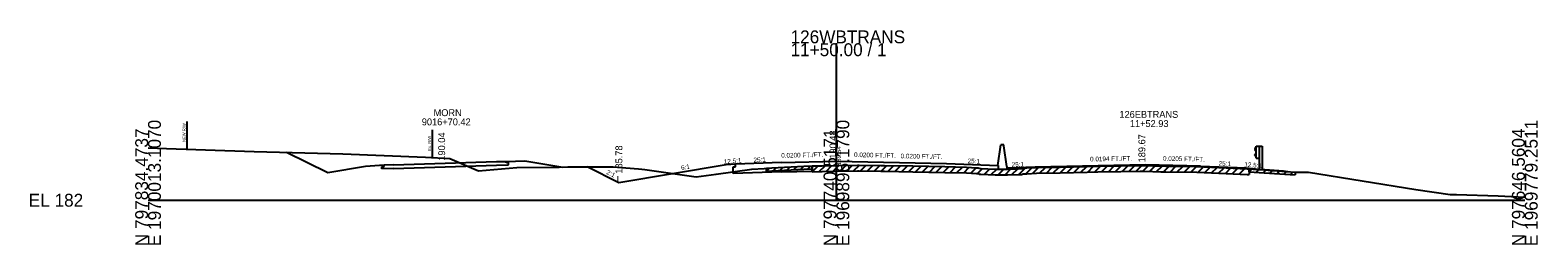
# Model space of a CAD drawing. Extents: x -6494 to 1970605, y -10 to 798140.
# Drawn here: x -25.7 to 302.8, y 3990.3 to 4037 of the extents above; entities that cross this region are included whole.
import ezdxf

# ---------------------------------------------------------------- set-up
doc = ezdxf.new("R2010")
doc.units = 0
for name, color, linetype in [('RD_GPK_XS_Cell', 7, 'Continuous'), ('RD_XS_Base', 7, 'Continuous'), ('RD_XS_EarthShd', 7, 'Continuous'), ('RD_XS_ExGround', 7, 'Continuous'), ('RD_XS_ExPaveRet', 7, 'Continuous'), ('RD_XS_ExRW', 7, 'Continuous'), ('RD_XS_GR', 7, 'Continuous'), ('RD_XS_MedBWall', 7, 'Continuous'), ('RD_XS_Misc_Line', 7, 'Continuous'), ('RD_XS_NewRW', 7, 'Continuous'), ('RD_XS_Pave', 7, 'Continuous'), ('RD_XS_PaveOvlay', 7, 'Continuous'), ('RD_XS_PaveShd', 7, 'Continuous'), ('RD_XS_TieSlope', 7, 'Continuous'), ('RD_XS_TX_Elev_EX', 7, 'Continuous'), ('RD_XS_TX_Elev_PR', 7, 'Continuous'), ('RD_XS_TX_Misc', 7, 'Continuous'), ('RD_XS_TX_MkPT', 7, 'Continuous'), ('RD_XS_TX_Profile', 7, 'Continuous'), ('RD_XS_TX_ShdSlope', 7, 'Continuous'), ('RD_XS_TX_Slope', 7, 'Continuous'), ('RD_XS_TX_Station', 7, 'Continuous')]:
    doc.layers.add(name, color=color, linetype=linetype)

msp = doc.modelspace()

# ---------------------------------------------------------------- linework, layer by layer
at = {"layer": 'RD_GPK_XS_Cell'}
for p, q in [((150, 4000), (150, 4034.13)), ((0, 4000), (150, 4000)), ((150, 4000), (300, 4000))]:
    msp.add_line(p, q, dxfattribs=at)
at = {"layer": 'RD_XS_Base'}
for p, q in [((78, 4008.15), (78, 4008.45)), ((78.51, 4008.17), (78, 4008.15)), ((78.51, 4007.69), (78.51, 4008.17)), ((50.93, 4007.31), (51.44, 4007.32)), ((50.93, 4006.83), (50.93, 4007.31)), ((53.48, 4006.91), (50.93, 4006.83)), ((51.44, 4007.32), (51.44, 4007.62)), ((75.96, 4007.61), (78.51, 4007.69)), ((127.5, 4007.26), (128, 4007.28)), ((127.5, 4005.78), (127.5, 4007.26)), ((138, 4006.2), (127.5, 4005.78)), ((128, 4007.28), (128, 4007.84)), ((138, 4006.2), (144.74, 4006.33)), ((239.31, 4006.86), (239.31, 4007.02))]:
    msp.add_line(p, q, dxfattribs=at)
at = {"layer": 'RD_XS_EarthShd'}
for p, q in [((78, 4008.45), (82.09, 4008.57)), ((51.44, 4007.62), (47.35, 4007.3)), ((128, 4007.84), (126, 4007.68)), ((239.31, 4007.02), (241.31, 4006.86))]:
    msp.add_line(p, q, dxfattribs=at)
at = {"layer": 'RD_XS_ExGround'}
msp.add_lwpolyline([(0, 4011.38), (3.99, 4011.25), (12.51, 4010.97), (23.11, 4010.57), (42.47, 4010.07), (60.48, 4009.38), (65.78, 4009.06), (72.02, 4006.38), (80.33, 4007.11), (89.59, 4007.21), (91.5, 4007.23), (94, 4007.23), (101.37, 4007.24), (106.9, 4006.8), (107.56, 4006.74), (108.24, 4006.65), (119.45, 4005.07), (123.82, 4005.67), (131.6, 4006.73), (134.25, 4006.93), (134.74, 4006.96), (135.95, 4007.03), (142.91, 4007.42), (146.9, 4007.48), (150.18, 4007.54), (154.61, 4007.64), (154.97, 4007.64), (159.69, 4007.56), (160.48, 4007.55), (166.66, 4007.46), (173.61, 4007.3), (178.32, 4007.2), (180.5, 4007.08), (180.85, 4007.06), (181.07, 4006.94), (181.44, 4006.92), (184.58, 4006.78), (186.51, 4006.78), (187.28, 4006.77), (189.62, 4006.85), (190.45, 4006.88), (190.68, 4006.98), (191.52, 4007.02), (193.56, 4007.1), (198.74, 4007.22), (204.64, 4007.36), (206.93, 4007.39), (211.99, 4007.47), (216.17, 4007.54), (216.88, 4007.55), (218.93, 4007.49), (220.7, 4007.45), (221.76, 4007.43), (228.56, 4007.32), (234.91, 4007.05), (239.53, 4006.85), (242.1, 4006.66), (249.97, 4006.11), (252.85, 4006.07), (276.23, 4002.33), (283.7, 4001.26), (285.15, 4001.25), (294.2, 4000.92), (300, 4000.7)], dxfattribs=at)
at = {"layer": 'RD_XS_ExPaveRet'}
for p, q in [((134.74, 4006.34), (134.74, 4006.96)), ((134.74, 4006.34), (135.95, 4006.41)), ((135.95, 4006.41), (142.91, 4006.79)), ((142.91, 4006.79), (144.74, 4006.82)), ((144.74, 4006.2), (144.74, 4007.45)), ((144.74, 4007.45), (144.74, 4006.82)), ((144.74, 4006.2), (146.9, 4006.23)), ((146.9, 4006.23), (150.18, 4006.29)), ((150.18, 4006.29), (154.61, 4006.39)), ((154.61, 4006.39), (154.97, 4006.39)), ((154.97, 4006.39), (159.69, 4006.31)), ((159.69, 4006.31), (160.48, 4006.3)), ((160.48, 4006.3), (166.66, 4006.21)), ((166.66, 4006.21), (173.61, 4006.05)), ((173.61, 4006.05), (178.32, 4005.95)), ((178.32, 4005.95), (180.5, 4005.83)), ((180.5, 4005.83), (180.85, 4005.81)), ((180.85, 4005.81), (181.07, 4005.69)), ((181.07, 4005.69), (181.44, 4005.67)), ((181.44, 4005.67), (184.58, 4005.53)), ((184.58, 4005.53), (186.51, 4005.53)), ((186.51, 4005.53), (187.28, 4005.52)), ((187.28, 4005.52), (189.62, 4005.6)), ((189.62, 4005.6), (190.45, 4005.63)), ((190.45, 4005.63), (190.68, 4005.73)), ((190.68, 4005.73), (191.52, 4005.77)), ((191.52, 4005.77), (193.56, 4005.85)), ((193.56, 4005.85), (198.74, 4005.97)), ((198.74, 4005.97), (204.64, 4006.11)), ((204.64, 4006.11), (206.93, 4006.14)), ((206.93, 4006.14), (211.99, 4006.22)), ((211.99, 4006.22), (216.17, 4006.29)), ((216.17, 4006.29), (216.88, 4006.3)), ((216.88, 4006.3), (218.93, 4006.24)), ((218.93, 4006.24), (220.7, 4006.2)), ((220.7, 4006.2), (221.76, 4006.18)), ((221.76, 4006.18), (228.56, 4006.07)), ((228.56, 4006.07), (234.91, 4005.8)), ((234.91, 4005.8), (239.53, 4005.6)), ((239.53, 4005.6), (239.95, 4005.57)), ((239.95, 4006.82), (239.95, 4005.57)), ((239.95, 4006.2), (239.95, 4006.82)), ((239.95, 4006.2), (242.1, 4006.03)), ((242.1, 4006.03), (249.97, 4005.49)), ((249.97, 4006.11), (249.97, 4005.49))]:
    msp.add_line(p, q, dxfattribs=at)
at = {"layer": 'RD_XS_ExRW'}
msp.add_line((61.9, 4015.34), (61.9, 4009.34), dxfattribs=at)
at = {"layer": 'RD_XS_GR'}
for p, q in [((241.46, 4011.58), (241.19, 4011.14)), ((241.46, 4011.74), (242.13, 4011.74)), ((241.46, 4009.17), (241.46, 4011.74)), ((242.13, 4011.74), (242.79, 4011.74)), ((242.13, 4011.74), (242.13, 4006.8)), ((242.79, 4011.74), (242.79, 4006.69)), ((241.19, 4011.14), (241.19, 4011.03)), ((241.19, 4011.03), (241.46, 4010.59)), ((241.19, 4009.88), (241.46, 4010.32)), ((241.19, 4009.77), (241.19, 4009.88)), ((241.46, 4009.33), (241.19, 4009.77)), ((241.46, 4009.17), (242.13, 4009.17))]:
    msp.add_line(p, q, dxfattribs=at)
at = {"layer": 'RD_XS_MedBWall'}
for p, q in [((185.16, 4007.57), (185.82, 4012.05)), ((186.49, 4012.05), (185.82, 4012.05)), ((186.49, 4011.85), (186.49, 4012.05)), ((187.16, 4007.37), (186.49, 4011.85)), ((187.16, 4007.37), (187.16, 4006.77))]:
    msp.add_line(p, q, dxfattribs=at)
at = {"layer": 'RD_XS_Misc_Line'}
for p, q in [((134.74, 4006.34), (135.41, 4007)), ((136.24, 4006.42), (136.9, 4007.08)), ((137.74, 4006.51), (138.41, 4007.17)), ((139.24, 4006.59), (139.91, 4007.25)), ((140.74, 4006.67), (141.41, 4007.33)), ((142.24, 4006.75), (142.91, 4007.42)), ((143.74, 4006.8), (144.38, 4007.44)), ((144.74, 4006.2), (146.02, 4007.47)), ((146.24, 4006.22), (147.52, 4007.49)), ((147.74, 4006.25), (149.02, 4007.52)), ((149.25, 4006.28), (150.52, 4007.55)), ((150.75, 4006.31), (152.02, 4007.58)), ((152.25, 4006.34), (153.52, 4007.61)), ((153.75, 4006.37), (155.02, 4007.64)), ((155.25, 4006.39), (156.47, 4007.62)), ((156.75, 4006.36), (157.97, 4007.59)), ((158.25, 4006.34), (159.47, 4007.56)), ((159.75, 4006.31), (160.98, 4007.54)), ((161.25, 4006.29), (162.48, 4007.52)), ((162.75, 4006.27), (163.98, 4007.5)), ((164.25, 4006.25), (165.48, 4007.48)), ((165.75, 4006.22), (166.98, 4007.45)), ((167.25, 4006.2), (168.47, 4007.42)), ((168.75, 4006.16), (169.97, 4007.39)), ((170.25, 4006.13), (171.47, 4007.35)), ((171.75, 4006.1), (172.97, 4007.32)), ((173.25, 4006.06), (174.47, 4007.29)), ((174.75, 4006.03), (175.97, 4007.25)), ((176.25, 4006), (177.47, 4007.22)), ((177.75, 4005.96), (178.95, 4007.17)), ((179.25, 4005.9), (180.43, 4007.08)), ((180.75, 4005.82), (181.84, 4006.9)), ((182.25, 4005.64), (183.45, 4006.83)), ((183.75, 4005.57), (184.96, 4006.78)), ((185.25, 4005.53), (186.5, 4006.78)), ((186.75, 4005.53), (188.02, 4006.8)), ((188.25, 4005.56), (189.54, 4006.85)), ((189.75, 4005.61), (191.15, 4007)), ((191.25, 4005.76), (192.56, 4007.06)), ((192.75, 4005.82), (194.05, 4007.12)), ((194.25, 4005.87), (195.53, 4007.15)), ((195.75, 4005.91), (197.03, 4007.18)), ((197.25, 4005.94), (198.53, 4007.22)), ((198.75, 4005.97), (200.03, 4007.26)), ((200.25, 4006.01), (201.53, 4007.29)), ((201.75, 4006.05), (203.03, 4007.33)), ((203.25, 4006.08), (204.53, 4007.36)), ((204.75, 4006.12), (206.02, 4007.38)), ((206.25, 4006.13), (207.52, 4007.4)), ((207.75, 4006.16), (209.02, 4007.43)), ((209.25, 4006.18), (210.52, 4007.45)), ((210.75, 4006.2), (212.02, 4007.48)), ((212.25, 4006.23), (213.52, 4007.5)), ((213.75, 4006.25), (215.02, 4007.52)), ((215.25, 4006.27), (216.52, 4007.54)), ((216.75, 4006.3), (217.98, 4007.52)), ((218.25, 4006.26), (219.47, 4007.48)), ((219.75, 4006.22), (220.98, 4007.44)), ((221.26, 4006.19), (222.48, 4007.42)), ((222.76, 4006.16), (223.99, 4007.39)), ((224.26, 4006.14), (225.49, 4007.37)), ((225.76, 4006.12), (226.99, 4007.35)), ((227.26, 4006.09), (228.49, 4007.32)), ((228.76, 4006.06), (229.96, 4007.26)), ((230.26, 4006), (231.46, 4007.2)), ((231.76, 4005.94), (232.96, 4007.13)), ((233.26, 4005.87), (234.46, 4007.07)), ((234.76, 4005.81), (235.96, 4007.01)), ((236.26, 4005.74), (237.46, 4006.94)), ((237.76, 4005.68), (238.96, 4006.88)), ((239.95, 4006.2), (240.53, 4006.78)), ((241.45, 4006.08), (242.04, 4006.66)), ((242.96, 4005.97), (243.54, 4006.56)), ((244.46, 4005.87), (245.04, 4006.45)), ((245.96, 4005.76), (246.54, 4006.35)), ((247.46, 4005.66), (248.04, 4006.25)), ((248.96, 4005.56), (249.54, 4006.14))]:
    msp.add_line(p, q, dxfattribs=at)
at = {"layer": 'RD_XS_NewRW'}
msp.add_line((8.44, 4017.1), (8.44, 4011.1), dxfattribs=at)
at = {"layer": 'RD_XS_Pave'}
for p, q in [((64.73, 4008.04), (75.96, 4008.39)), ((138, 4008.24), (150, 4008.48)), ((150, 4008.48), (174, 4008)), ((53.48, 4007.69), (64.73, 4008.04)), ((53.48, 4006.91), (64.73, 4007.26)), ((64.73, 4007.26), (75.96, 4007.61)), ((217.31, 4007.67), (193.3, 4007.2)), ((229.31, 4007.42), (217.31, 4007.67))]:
    msp.add_line(p, q, dxfattribs=at)
at = {"layer": 'RD_XS_PaveOvlay'}
for p, q in [((144.74, 4007.45), (146.9, 4007.48)), ((144.74, 4007.45), (144.74, 4006.33)), ((146.9, 4007.48), (150.18, 4007.54)), ((150.18, 4007.54), (154.61, 4007.64)), ((154.61, 4007.64), (154.97, 4007.64)), ((154.97, 4007.64), (159.69, 4007.56)), ((159.69, 4007.56), (160.48, 4007.55)), ((160.48, 4007.55), (166.66, 4007.46)), ((166.66, 4007.46), (173.61, 4007.3)), ((173.61, 4007.3), (178.32, 4007.2)), ((178.32, 4007.2), (180.5, 4007.08)), ((180.5, 4007.08), (180.85, 4007.06)), ((180.85, 4007.06), (181.07, 4006.94)), ((181.07, 4006.94), (181.44, 4006.92)), ((181.44, 4006.92), (184.58, 4006.78)), ((184.58, 4006.78), (185.22, 4006.78))]:
    msp.add_line(p, q, dxfattribs=at)
at = {"layer": 'RD_XS_PaveShd'}
for p, q in [((75.96, 4008.39), (78, 4008.45)), ((138, 4008.24), (128, 4007.84)), ((53.48, 4007.69), (51.44, 4007.62)), ((174, 4008), (185.22, 4007.55)), ((185.22, 4007.55), (185.22, 4006.78)), ((193.3, 4007.2), (187.16, 4006.96)), ((229.31, 4007.42), (239.31, 4007.02))]:
    msp.add_line(p, q, dxfattribs=at)
at = {"layer": 'RD_XS_TieSlope'}
for p, q in [((39.17, 4005.97), (30.14, 4010.39)), ((82.09, 4008.57), (90.39, 4007.22)), ((47.35, 4007.3), (39.17, 4005.97)), ((102.6, 4003.78), (95.69, 4007.23)), ((126, 4007.68), (102.6, 4003.78)), ((241.31, 4006.86), (247.44, 4006.37)), ((247.44, 4006.37), (248.34, 4006.22))]:
    msp.add_line(p, q, dxfattribs=at)

# ---------------------------------------------------------------- texts
at = {"layer": 'RD_GPK_XS_Cell'}
for s, p in [('126WBTRANS', (140, 4034.13)), ('11+50.00 / 1', (140, 4031.33)), ('EL 182', (-26, 3998.6))]:
    msp.add_text(s, height=2.8, dxfattribs=at).set_placement(p)
for s, p in [('N 797834.4737', (0, 3990)), ('E 1970013.1070', (2.8, 3990)), ('N 797740.5171', (150, 3990)), ('E 1969896.1790', (152.8, 3990)), ('N 797646.5604', (300, 3990)), ('E 1969779.2511', (302.8, 3990))]:
    msp.add_text(s, height=2.8, rotation=90, dxfattribs=at).set_placement(p)
at = {"layer": 'RD_XS_ExRW'}
msp.add_text('Ex. R/W ', height=0.65, rotation=90, dxfattribs=at).set_placement((61.65, 4010.72))
at = {"layer": 'RD_XS_NewRW'}
msp.add_text('NEW R/W ', height=0.65, rotation=90, dxfattribs=at).set_placement((8.17, 4012.66))
at = {"layer": 'RD_XS_TX_Elev_EX'}
msp.add_text('189.54', height=1, rotation=90, dxfattribs=at).set_placement((151, 4007.54))
at = {"layer": 'RD_XS_TX_Elev_PR'}
for s, p in [(' 190.04', (64.73, 4008.04)), (' 190.48', (150, 4008.48)), (' 189.67', (217.31, 4007.67))]:
    msp.add_text(s, height=1.5, rotation=90, dxfattribs=at).set_placement(p)
at = {"layer": 'RD_XS_TX_Misc'}
msp.add_text('185.78', height=1.5, rotation=90, dxfattribs=at).set_placement((103.35, 4005.78))
at = {"layer": 'RD_XS_TX_MkPT'}
msp.add_text('L', height=1.5, dxfattribs=at).set_placement((102.09, 4003.78))
at = {"layer": 'RD_XS_TX_Profile'}
for rotation, p in [(2.2906, (131.94, 4008.24)), (357.7094, (178.57, 4008.06)), (2.2899, (188.2, 4007.25)), (357.7101, (233.27, 4007.52))]:
    msp.add_text('25:1', height=1, rotation=rotation, dxfattribs=at).set_placement(p)
at = {"layer": 'RD_XS_TX_ShdSlope'}
for rotation, p in [(4.5739, (125.5, 4007.89)), (355.4275, (238.86, 4007.31))]:
    msp.add_text('12.5:1', height=1, rotation=rotation, dxfattribs=at).set_placement(p)
at = {"layer": 'RD_XS_TX_Slope'}
for s, rotation, p in [('0.0200 FT./FT.', 1.1458, (137.98, 4009.24)), ('0.0200 FT./FT.', 358.8542, (153.83, 4009.4)), ('0.0200 FT./FT.', 358.8542, (163.97, 4009.13)), ('0.0194 FT./FT.', 1.1142, (205.28, 4008.44)), ('0.0205 FT./FT.', 358.8242, (221.14, 4008.59)), ('2:1', 333.4349, (99.77, 4005.75)), ('6:1', 9.4623, (116.22, 4006.55))]:
    msp.add_text(s, height=1, rotation=rotation, dxfattribs=at).set_placement(p)
at = {"layer": 'RD_XS_TX_Station'}
for s, p in [('MORN', (62.22, 4018.29)), ('126EBTRANS', (211.66, 4017.92)), ('9016+70.42', (59.65, 4016.29)), ('11+52.93', (213.94, 4015.92))]:
    msp.add_text(s, height=1.5, dxfattribs=at).set_placement(p)

doc.saveas('drawing.dxf')
